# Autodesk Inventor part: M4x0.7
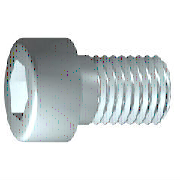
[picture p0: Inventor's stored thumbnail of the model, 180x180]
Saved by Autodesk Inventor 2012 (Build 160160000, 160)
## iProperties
Created: 2009-02
Part Number: M4x0.7
Material: 강, 연강
Description: 6각머리 태핑 나사
Document SubType Name: Modeling
Standard: KS B 1003
Standards Organization: KS
Language: ko-KR
Size Designation: M 4 x 12
Categories: <MemberInstance><Categories><Category DisplayName="조임쇠" InternalName="e4da775c-781d-43d5-af7c-5136215cf5a6" Mnemonic="FSTN"><Category DisplayName="볼트" InternalN
Density: 1 g/cm^3
Checked By: KYOUNG IL JANG
Vendor: CBT Solutions
Designer: KYOUNG IL JANG
Manager: KYOUNG IL JANG
Company: 한국ATC센터
IsCustomPart: 0
Author: KYOUNG IL JANG
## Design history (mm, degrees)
body "Solid1"
workplane "Work Plane1"
fillet "Fillet2" dims "d30" = 0.1 (= R)
revolve "본체" stored, may be unused: angle "d10" = 90 deg
sketch "스케치2"
  geometry: L1 (0, -4.9)-(0, 4.9) reference; L2 (-4.9, 0)-(4.9, 0) reference; L3 (1.732, 0)-(0.866, -1.5); L4 (0.866, -1.5)-(-0.866, -1.5); L5 (-0.866, -1.5)-(-1.732, 0); L6 (-1.732, 0)-(-0.866, 1.5); L7 (-0.866, 1.5)-(0.866, 1.5); L8 (0.866, 1.5)-(1.732, 0); 2 further points
  constraints: 12 end point, 1 coincident, 1 horizontal alignment, 1 point on line, 12 other
extrude "슬롯" join sketch "스케치2" stored distance "d11" = 10; taper "d12" = 0 deg
fillet "모깎기1" dims "d17" = 0.4 (= RR)
feature "스레드" dims "d13" = 10.25 (= GEL), "d14" = 0
chamfer "모따기1" distance "d15" = 0.42941 (= -0.5 x SPD + 0.5 x GD); stored, may be unused: second distance "d16" = 0.42941 (= GUL), angle "d27" = 45 deg
sketch "스케치1"
  geometry: L1 (-1, 0)-(12, 0); L2 (12, 0)-(12, 2); L3 (12, 2)-(1.75, 2); L4 (1.75, 2)-(1.32, 2); L5 (1.32, 2)-(0, 2); L6 (0, 2)-(0, 3.5); L7 (0, 3.5)-(-4, 3.5); L8 (-4, 3.5)-(-4, 1.732); L9 (-4, 1.732)-(-2, 1.732); L10 (-2, 1.732)-(-1, 0); L11 (-7.2, 0)-(15.2, 0) reference; L12 (0, -0.7)-(0, 4.2) reference; L13 (1.75, 2)-(0, 2)
  constraints: 22 end point, 6 parallel, 2 collinear, 2 perpendicular, 1 horizontal, 1 point on line
  dimensions: "d1" = 10.25 distance from line of L3.end L2 (= GEL); "d2" = 0.42952 distance of L4.end L3.end (computed from GAL); "d3" = 4 distance between parallel lines of L8 L6 (= KOH); "d4" = 2 distance of L8.end L9.end (= INTI); "d5" = 60 deg angle of L10 L1; "d6" = 4 diameter of L3 L1 (= GD); "d7" = 4 diameter of L5 L1 (= BDM); "d8" = 3.4641 diameter of L9 L1 (= 1.1547 x SW); "d9" = 7 diameter of L7 L1 (= KOD); "d26" = 12 distance between parallel lines of L12 L2 (= NLG)
other parameters: "GD" = 4 (= NND) [user parameter; used in 2 equation terms], "NLG" = 12 [user parameter; used in 1 equation term], "GEL" = 10.25 [user parameter; used in 2 equation terms], "KOD" = 7 [user parameter; used in 1 equation term], "KOH" = 4 [user parameter; used in 1 equation term], "INTI" = 2 [user parameter; used in 1 equation term], "GAL" = 0.42941 (= 0.61345 x PTC) [user parameter; used in 1 equation term], "GUL" = 0.42941 (= 0.61345 x PTC) [user parameter; used in 1 equation term], "BDM" = 4 (= NND) [user parameter; used in 1 equation term], "SW" = 3 [user parameter; used in 2 equation terms], "RR" = 0.4 [user parameter; used in 1 equation term], "SPD" = 3.14117 (= NND - 1.2269 x PTC) [user parameter; used in 1 equation term], "d19" = 0, "d28" = 0, "d29" = 0, "R" = 0.1 [user parameter; used in 1 equation term], "PHH" = 0.2 [user parameter], "GD1" = 3.14117 (= THREADDIA - 1.2269 x PTC) [user parameter], "THREADDIA" = 4 [user parameter; used in 1 equation term], "FAWI" = 45 deg [user parameter], "TPU" = 14.28571 (computed from PTC) [user parameter], "PTC" = 0.7 [user parameter; used in 5 equation terms], "NND" = 4 [user parameter; used in 3 equation terms], "TOA" = 30 deg [user parameter], "E0" = 3.465 (= 1.155 x SW) [user parameter]
